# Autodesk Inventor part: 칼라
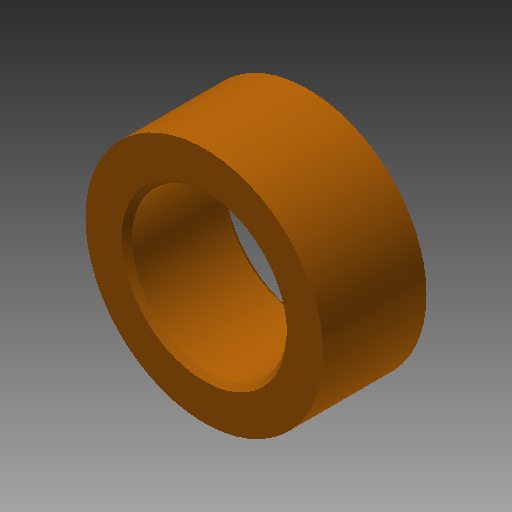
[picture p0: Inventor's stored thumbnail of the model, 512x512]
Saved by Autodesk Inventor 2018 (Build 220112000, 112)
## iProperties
Created: 2015-09
Part Number: 칼라
Document SubType Name: Modeling
Designer: mduedu
Density: 1 g/cm^3
Material: 스테인리스강
Appearance: 주황색
Author: mduedu
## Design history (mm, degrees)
node "작업 평면1"
node "작업 평면2"
sketch "스케치1"
  geometry: C1 r 7.5 at (0, 0); C2 r 11.5 at (0, 0); 1 further point
  constraints: 2 centre point, 2 coincident
  dimensions: "d0" = 15 diameter of C1; "d1" = 23 diameter of C2
extrude "돌출1" new body sketch "스케치1" stored distance "d2" = 9.85; taper "d3" = 0 deg
chamfer "모따기1" distance "d4" = 0.5; stored, may be unused: second distance "d5" = 2, angle "d6" = 45 deg
node "솔리드1"
